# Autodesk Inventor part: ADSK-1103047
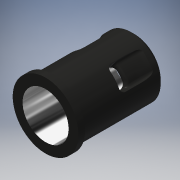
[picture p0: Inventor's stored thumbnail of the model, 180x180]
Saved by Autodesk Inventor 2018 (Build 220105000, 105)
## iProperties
Shininess: 54.0
Length Units: 11269
Angle Units: 11279
Time Units: 11290
Mass Units: 11286
Length Display Precision: 2
Angle Display Precision: 2
Compacted: True
Created: 2000-07
Part Number: ADSK-1103047
Document SubType Name: Modeling
Description: ENGINE SLEEVE - REAR
Mass: 20.4003 g
Surface Area: 29.807 cm^2
Volume: 2.59876 cm^3
Density: 7.85 g/cm^3
Material: Cast Steel
Appearance: Brass
Density: 0.0
Volumn: 0.0
Area: 0.0
PropertySet Name: Model Information
Control State: 0
Master: False
Checked Out: False
Author: Autodesk, Inc.
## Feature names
1. Extrusion3
2. Fillet1
3. Revolution1
4. Fillet2
5. Sweep1
6. Fillet3
7. Fillet4
8. Mirror1
## Parameters: d0 = 18 mm, d1 = 14 mm, d2 = 27 mm, d3 = 0, d5 = 2 mm, d6 = 0, d7 = 1 mm, d8 = 1 mm, d9 = 45 deg, d10 = 0, d11 = 0, d12 = 0, d13 = 0, d15 = 0, d16 = 2 mm, d17 = -40 deg, d18 = 3 mm, d19 = 45 deg, d20 = 1.5 mm, d21 = 45 deg, d22 = 1 mm, d23 = 0, d24 = 1 mm, d25 = 1 mm, d26 = 0
